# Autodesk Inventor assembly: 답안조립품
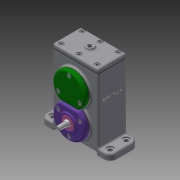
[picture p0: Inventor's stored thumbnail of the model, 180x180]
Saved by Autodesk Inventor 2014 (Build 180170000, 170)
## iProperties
Created: 2020-05
Part Number: 답안조립품
Document SubType Name: Assembly
Designer: kh
Mass: 1076.75 g
Surface Area: 1575.48 cm^2
Volume: 384.079 cm^3
Density: 2.80345 g/cm^3
Author: kh
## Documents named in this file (24)
- C:\Users\kh\Desktop\600506V1033\답안조립품.iam
- C:\Users\kh\Desktop\600506V1033\본체.ipt
- C:\Users\kh\Desktop\600506V1033\개스킷 A.ipt
- C:\Users\kh\Desktop\600506V1033\개스킷 B.ipt
- C:\Users\kh\Desktop\600506V1033\개스킷 C.ipt
- C:\Users\kh\Desktop\600506V1033\베어링 6001.ipt
- 베어링 6001.ipt
- C:\Users\kh\Desktop\600506V1033\베어링 6002.ipt
- 베어링 6002.ipt
- C:\Users\kh\Desktop\600506V1033\볼트 M4.ipt
- C:\Users\kh\Desktop\600506V1033\스퍼기어 A.ipt
- C:\Users\kh\Desktop\600506V1033\스퍼기어 B.ipt
- C:\Users\kh\Desktop\600506V1033\오일 실 10 20 7.ipt
- C:\Users\kh\Desktop\600506V1033\오일 실 12 22 7.ipt
- C:\Users\kh\Desktop\600506V1033\축 A.ipt
- C:\Users\kh\Desktop\600506V1033\축 B.ipt
- C:\Users\kh\Desktop\600506V1033\칼라.ipt
- C:\Users\kh\Desktop\600506V1033\커버 A.ipt
- C:\Users\kh\Desktop\600506V1033\커버 B.ipt
- C:\Users\kh\Desktop\600506V1033\커버 C.ipt
- C:\Users\kh\Desktop\600506V1033\커버 D.ipt
- C:\Users\kh\Desktop\600506V1033\커버 E.ipt
- C:\Users\kh\Desktop\600506V1033\키 4 x 4 x 12.ipt
- C:\Users\kh\Desktop\600506V1033\키 5 x 5 x 12.ipt
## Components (5 placed, 3 different names)
1. 개스킷 A:1
2. 개스킷 C:1
3. 개스킷 B:1
4. 개스킷 B:2
5. 개스킷 B:3
